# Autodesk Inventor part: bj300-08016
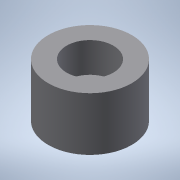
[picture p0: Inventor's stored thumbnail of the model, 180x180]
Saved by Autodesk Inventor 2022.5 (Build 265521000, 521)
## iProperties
Created: 2016-12
Part Number: bj300-08016
Material: 一般
Document SubType Name: Modeling
Designer: imaocorp
Density: 1 g/cm^3
Appearance: 既定
Author: imaocorp
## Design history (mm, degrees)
node "bj300-08016.x_t1"
node "bj300-08016"
node "Base1"
